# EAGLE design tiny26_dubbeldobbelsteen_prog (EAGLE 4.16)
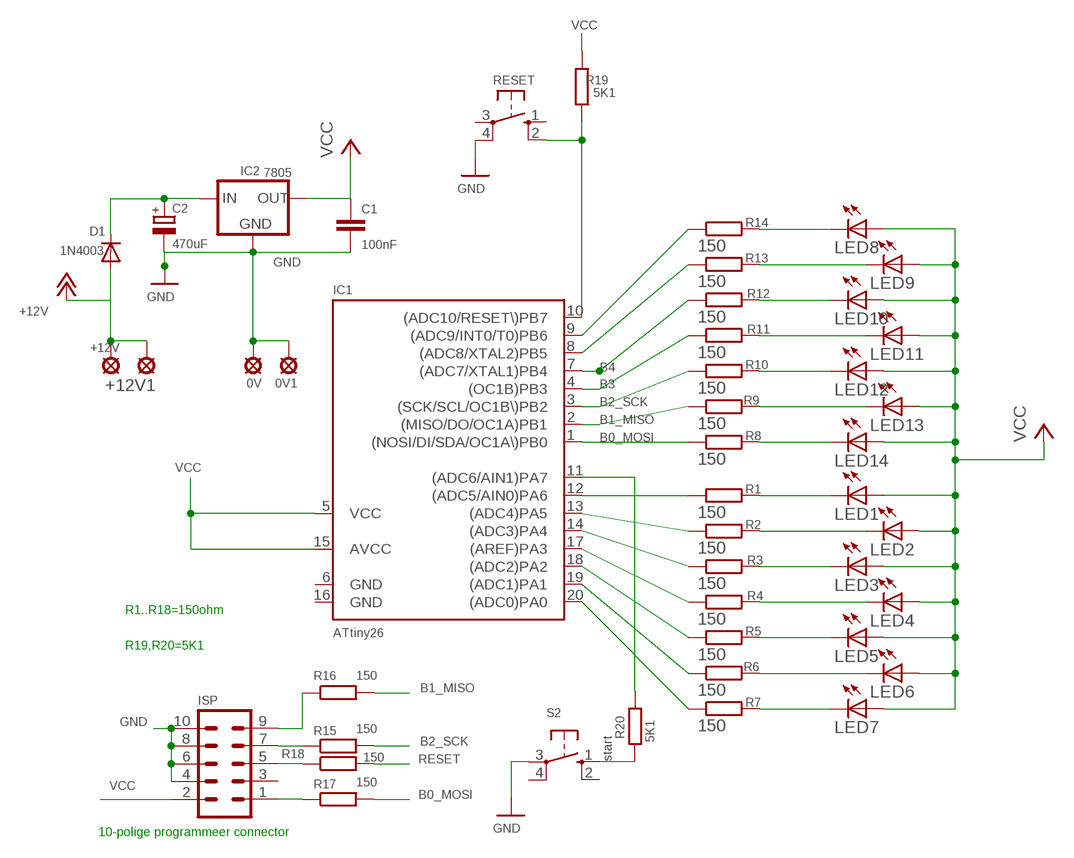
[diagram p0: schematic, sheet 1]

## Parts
0V  SE14  [SE14]
0V1  SE14  [SE14]
+12V  SE14  [SE14]
+12V1  SE14  [SE14]
C1  100nF  C-EU050-025X075  [C050-025X075]
C2  470uF  CPOL-EUE5-6  [E5-6]
D1  1N4003  DIODE-D-12.5  [D-12.5]
IC1  ATtiny26  TINY26LP  [DIL20]
IC2  7805  78XXS  [78XXS]
ISP  MA05-2  [MA05-2]
LED1  LED3MM  [LED3MM]
LED2  LED3MM  [LED3MM]
LED3  LED3MM  [LED3MM]
LED4  LED3MM  [LED3MM]
LED5  LED3MM  [LED3MM]
LED6  LED3MM  [LED3MM]
LED7  LED3MM  [LED3MM]
LED8  LED3MM  [LED3MM]
LED9  LED3MM  [LED3MM]
LED10  LED3MM  [LED3MM]
LED11  LED3MM  [LED3MM]
LED12  LED3MM  [LED3MM]
LED13  LED3MM  [LED3MM]
LED14  LED3MM  [LED3MM]
R1  150  R-EU_0207/10  [0207/10]
R2  150  R-EU_0207/10  [0207/10]
R3  150  R-EU_0207/10  [0207/10]
R4  150  R-EU_0207/10  [0207/10]
R5  150  R-EU_0207/10  [0207/10]
R6  150  R-EU_0207/10  [0207/10]
R7  150  R-EU_0207/10  [0207/10]
R8  150  R-EU_0207/10  [0207/10]
R9  150  R-EU_0207/10  [0207/10]
R10  150  R-EU_0207/10  [0207/10]
R11  150  R-EU_0207/10  [0207/10]
R12  150  R-EU_0207/10  [0207/10]
R13  150  R-EU_0207/10  [0207/10]
R14  150  R-EU_0207/10  [0207/10]
R15  150  R-EU_0207/10  [0207/10]
R16  150  R-EU_0207/10  [0207/10]
R17  150  R-EU_0207/10  [0207/10]
R18  150  R-EU_0207/10  [0207/10]
R19  5K1  R-EU_0207/10  [0207/10]
R20  5K1  R-EU_0207/10  [0207/10]
RESET  10-XX  [B3F-10XX]
S2  start  10-XX  [B3F-10XX]

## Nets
+12V: +12V1.MP +12V.MP D1.A
B0_MOSI: IC1.1((NOSI/DI/SDA/OC1A\)PB0) R8.1 R17.2
B1_MISO: IC1.2((MISO/DO/OC1A)PB1) R9.1 R16.2
B2_SCK: IC1.3((SCK/SCL/OC1B\)PB2) R10.1 R15.2
B3: IC1.4((OC1B)PB3) R11.1
B4: IC1.7((ADC7/XTAL1)PB4) R12.1
GND: 0V1.MP 0V.MP C1.2 C2.- IC2.GND ISP.4 ISP.6 ISP.8 ISP.10 RESET.4(P1) S2.3(P)
N$1: ISP.1 R17.1
N$3: R20.1 S2.1(S)
N$4: ISP.5 R18.1
N$5: LED7.K(C) R7.2
N$6: LED6.K(C) R6.2
N$7: LED5.K(C) R5.2
N$8: LED4.K(C) R4.2
N$9: LED3.K(C) R3.2
N$10: C2.+ D1.C IC2.IN
N$11: LED2.K(C) R2.2
N$12: LED1.K(C) R1.2
N$13: ISP.7 R15.1
N$14: IC1.20((ADC0)PA0) R7.1
N$15: IC1.19((ADC1)PA1) R6.1
N$16: ISP.9 R16.1
N$17: IC1.18((ADC2)PA2) R5.1
N$18: IC1.17((AREF)PA3) R4.1
N$19: IC1.14((ADC3)PA4) R3.1
N$20: IC1.13((ADC4)PA5) R2.1
N$21: IC1.12((ADC5/AIN0)PA6) R1.1
N$23: LED14.K(C) R8.2
N$24: LED13.K(C) R9.2
N$25: LED12.K(C) R10.2
N$26: LED11.K(C) R11.2
N$27: LED10.K(C) R12.2
N$28: LED9.K(C) R13.2
N$29: LED8.K(C) R14.2
N$30: IC1.8((ADC8/XTAL2)PB5) R13.1
N$31: IC1.9((ADC9/INT0/T0)PB6) R14.1
N$62: IC1.11((ADC6/AIN1)PA7) R20.2
RESET: IC1.10((ADC10/RESET\)PB7) R18.2 R19.1 RESET.2(S1)
VCC: C1.1 IC1.5(VCC) IC1.15(AVCC) IC2.OUT ISP.2 LED1.A LED2.A LED3.A LED4.A LED5.A LED6.A LED7.A LED8.A LED9.A LED10.A LED11.A LED12.A LED13.A LED14.A R19.2
Unconnected: ISP.3 RESET.1(S) RESET.3(P) S2.2(S1) S2.4(P1)

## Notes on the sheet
- R1..R18=150ohm
- R19,R20=5K1
- 10-polige programmeer connector

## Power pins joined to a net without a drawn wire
GND: IC1.6(GND) IC1.16(GND)

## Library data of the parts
0V 0V1 +12V +12V1 = solpad:SE14: SOLDER PAD
C1 = rcl:C-EU: CAPACITOR, European symbol
C2 = rcl:CPOL-EU: POLARIZED CAPACITOR, European symbol
D1 = diode:DIODE-: DIODE
IC1 = atmel:TINY26*: 8-bit AVR Microcontroller with 2K Bytes Flash
IC2 = v-reg:78XXS: VOLTAGE REGULATOR
ISP = con-lstb:MA05-2: PIN HEADER
LED1-LED14 = led:LED: LED
R1-R20 = rcl:R-EU_: RESISTOR, European symbol
RESET S2 = switch-omron:10-XX: OMRON SWITCH

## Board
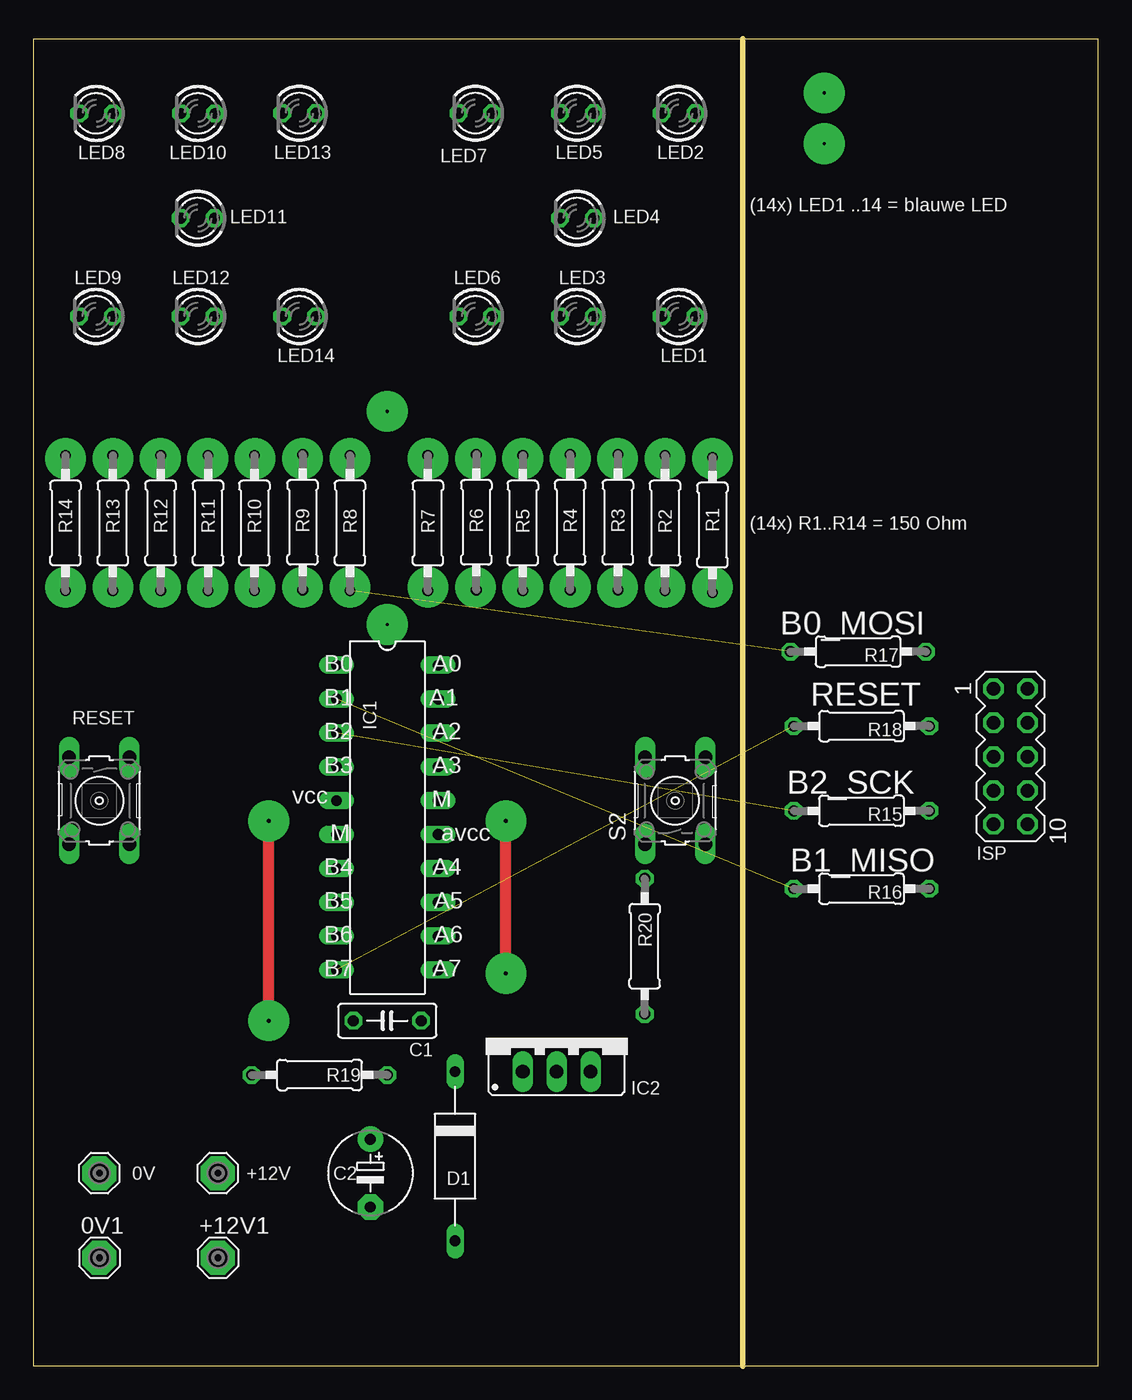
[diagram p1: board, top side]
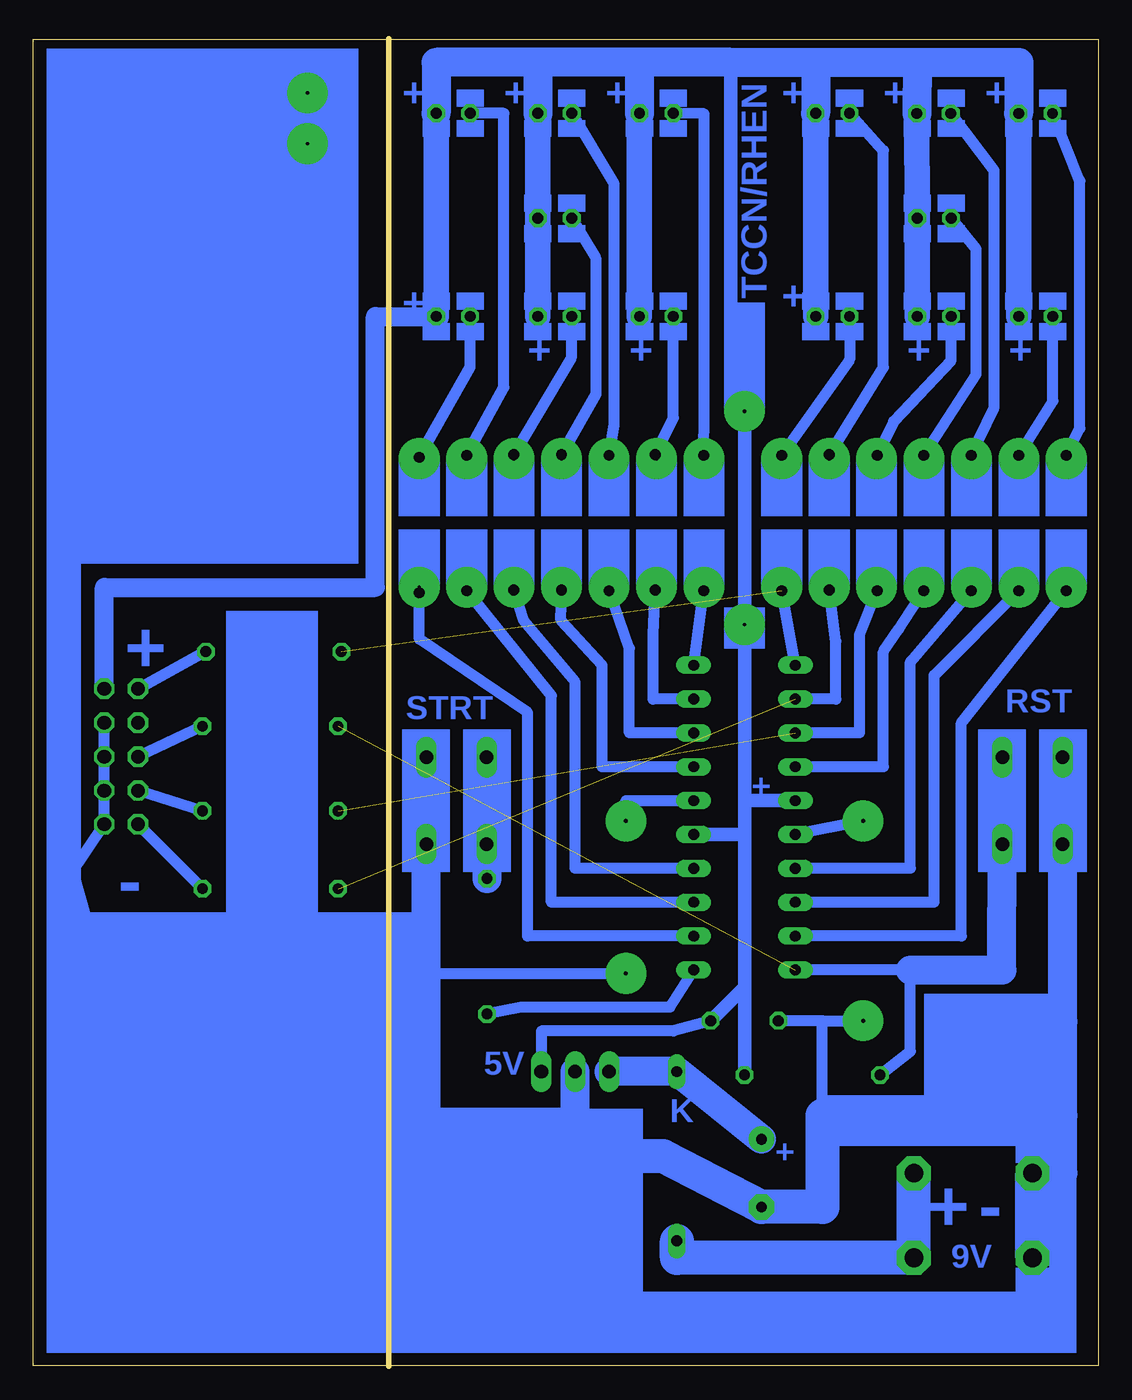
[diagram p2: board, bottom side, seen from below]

Size 79.86 x 99.57 mm. Coordinates in mm from the lower left corner, seen from the top.
Outline: 53.21,99.57 53.21,0
Outline: 0,0.04 79.86,0.04 79.86,99.53 0,99.53 0,0.04
Copper layers (1*16): Top 0.035mm / dielectric 1.5mm / Bottom 0.035mm
Design rules "default": minimum track width 24mil, minimum drill 24mil, track to track 15mil, track to pad 15mil, pad to pad 15mil, via to via 15mil, smd to smd 8mil, copper to edge 15mil, drill to drill 8mil, minimum pad ring 10mil, minimum via ring 8mil, stop-mask expansion 4mil, vias tented up to drill 0mil, thermal gap 10mil

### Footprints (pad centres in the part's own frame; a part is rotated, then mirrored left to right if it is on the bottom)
SE14 = drill 1.397 pad 2.54 octagon: MP 0,0
C050-025X075 = drill 0.813 octagon: 1 -2.54,0; 2 2.54,0
E5-6 = drill 0.813 pad 1.905 round: + -2.54,0 | drill 0.813 pad 1.905 octagon: - 2.54,0
D-12.5 = drill 0.813 long: A 6.35,0; C -6.35,0
DIL20 = drill 0.813 long: 1 -11.43,-3.81; 2 -8.89,-3.81; 3 -6.35,-3.81; 4 -3.81,-3.81; 5 -1.27,-3.81; 6 1.27,-3.81; 7 3.81,-3.81; 8 6.35,-3.81; 9 8.89,-3.81; 10 11.43,-3.81; 11 11.43,3.81; 12 8.89,3.81; 13 6.35,3.81; 14 3.81,3.81; 15 1.27,3.81; 16 -1.27,3.81; 17 -3.81,3.81; 18 -6.35,3.81; 19 -8.89,3.81; 20 -11.43,3.81
78XXS = drill 1.016 long: GND 0,-2.54; IN -2.54,-2.54; OUT 2.54,-2.54
MA05-2 = drill 1.016 octagon: 1 -5.08,-1.27; 2 -5.08,1.27; 3 -2.54,-1.27; 4 -2.54,1.27; 5 0,-1.27; 6 0,1.27; 7 2.54,-1.27; 8 2.54,1.27; 9 5.08,-1.27; 10 5.08,1.27
LED3MM = drill 0.813 octagon: A -1.27,0; K 1.27,0
0207/10 = drill 0.813 octagon: 1 -5.08,0; 2 5.08,0
B3F-10XX = drill 1.016 long: 1 -3.251,2.261; 2 3.251,2.261; 3 -3.251,-2.261; 4 3.251,-2.261

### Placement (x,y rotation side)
0V  4.95,14.48 180 top
0V1  4.95,8.13 0 top
+12V  13.84,14.48 180 top
+12V1  13.84,8.13 0 top
C1  26.54,25.91 180 top
C2  25.27,14.48 270 top
D1  31.62,15.75 270 top
IC1  26.54,41.15 270 top
IC2  39.24,24.64 0 top
ISP  73.27,45.72 270 top
LED1  48.38,78.74 180 top
LED2  48.38,93.98 180 top
LED3  40.76,78.74 180 top
LED4  40.76,86.11 180 top
LED5  40.76,93.98 180 top
LED6  33.14,78.74 180 top
LED7  33.14,93.98 180 top
LED8  4.71,93.96 180 top
LED9  4.69,78.74 180 top
LED10  12.35,93.96 180 top
LED11  12.31,86.11 180 top
LED12  12.31,78.74 180 top
LED13  19.93,93.98 180 top
LED14  19.93,78.74 180 top
R1  50.92,63.09 90 top
R2  47.37,63.25 90 top
R3  43.84,63.3 90 top
R4  40.25,63.3 90 top
R5  36.7,63.25 90 top
R6  33.22,63.3 90 top
R7  29.59,63.25 90 top
R8  23.74,63.25 90 top
R9  20.19,63.3 90 top
R10  16.58,63.25 90 top
R11  13.1,63.25 90 top
R12  9.55,63.25 90 top
R13  5.96,63.25 90 top
R14  2.41,63.25 90 top
R15  62.1,41.66 180 top
R16  62.1,35.81 180 top
R17  61.84,53.59 180 top
R18  62.1,48.01 180 top
R19  21.46,21.84 0 top
R20  45.84,31.5 270 top
RESET  4.95,42.42 270 top
S2  48.13,42.42 90 top

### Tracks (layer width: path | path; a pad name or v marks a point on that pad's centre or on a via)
+12V
  Bottom 2.54: +12V.MP +12V1.MP 31.62,8.13 D1.A
B0_MOSI  (1 unrouted)
  Bottom 0.813: IC1.1 R8.1
B1_MISO  (1 unrouted)
  Bottom 0.813: IC1.2 19.68,50.04 19.68,54.36 R9.1
B2_SCK  (1 unrouted)
  Bottom 0.813: IC1.3 17.9,47.5 17.9,54.86 R10.1
B3
  Bottom 0.813: IC1.4 16.12,44.96 16.12,53.59 14.96,55.3 R11.1
B4
  Bottom 0.813: IC1.7 14.09,37.34 14.09,52.83 R12.1
GND  (via drill 0.3 pad 3.05)
  Top 0.813: v35.43,29.46 v35.43,40.89 | v17.65,25.91 v17.65,40.89
  Bottom 0.406: 2.66,18.8 20.7,18.8
  Bottom 0.813: v35.43,40.89 35.43,42.42 IC1.16 | v17.65,40.89 IC1.6 | 50.41,29.46 v35.43,29.46 | 20.7,25.91 v17.65,25.91 | 20.7,18.8 20.7,25.91 | 20.7,25.91 C1.2 | 35.43,15.75 35.43,18.29 39.24,18.29 | ISP.4 ISP.6 ISP.8 ISP.10 77.08,36.83
  Bottom 1.422: 77.08,36.83 75.31,30.48 50.67,30.48 50.41,30.48
  Bottom 2.184: S2.3 50.41,30.48 50.41,29.46 50.41,18.29 39.24,18.29 IC2.GND | RESET.4 2.66,25.83 2.66,18.8 2.66,14.48 0V.MP
  Bottom 2.54: 35.43,15.75 32.63,15.75 C2.- 20.7,11.94 20.7,18.8 | 0V1.MP 0V.MP
N$1
  Bottom 0.813: R17.1 ISP.1
N$2  (via drill 0.25 pad 3.05)
  other vias: 2.41,68.07
N$3
  Bottom 0.813: 45.84,39.12 S2.1
  Bottom 2.184: R20.1 45.84,39.12
N$4
  Bottom 0.813: R18.1 ISP.5
N$5
  Bottom 0.813: LED7.K 29.56,93.93 29.56,71.58 R7.2
N$6
  Bottom 0.813: R6.2 31.87,71.12 LED6.K
N$7
  Bottom 0.813: LED5.K 36.32,88.67 36.32,70.61 R5.2
N$8
  Bottom 0.813: LED4.K 37.66,83.06 37.66,72.9 R4.2
N$9
  Bottom 0.813: LED3.K 39.49,75.69 R3.2
N$10
  Bottom 2.184: C2.+ D1.C IC2.IN
N$11
  Bottom 0.813: LED2.K 44.57,93.98 44.57,73.41 R2.2
N$12
  Bottom 0.813: R1.2 47.11,74.93 LED1.K
N$13
  Bottom 0.813: R15.1 ISP.7
N$14
  Bottom 0.813: IC1.20 R7.1
N$15
  Bottom 0.813: IC1.19 33.4,50.04 33.4,54.86 R6.1
N$16
  Bottom 0.813: R16.1 ISP.9
N$17
  Bottom 0.813: IC1.18 35.17,47.5 35.17,53.85 R5.1
N$18
  Bottom 0.813: IC1.17 37.21,44.96 37.21,52.58 40.3,55.96 R4.1
N$19
  Bottom 0.813: IC1.14 39.24,37.34 39.24,51.31 43.07,55.91 R3.1
N$20
  Bottom 0.813: IC1.13 41.02,34.8 41.02,50.29 R2.1
N$21
  Bottom 0.813: IC1.12 42.79,32.26 42.79,49.02 50.92,54.53 R1.1
N$22  (via drill 0.25 pad 3.05)
  other vias: 5.96,68.07
N$23
  Bottom 0.813: LED14.K 18.66,75.51 R8.2
N$24
  Bottom 0.813: LED13.K 16.12,91.19 16.12,74.93 R9.2
N$25
  Bottom 0.813: R10.2 15.36,70.87 11.04,75.44 LED12.K
N$26
  Bottom 0.813: R11.2 9.16,74.4 9.16,83.8 LED11.K
N$27
  Bottom 0.813: LED10.K 7.82,89.69 7.82,71.91 R12.2
N$28
  Bottom 0.813: LED9.K 3.42,72.39 R13.2
N$29
  Bottom 0.813: LED8.K 1.39,88.9 1.39,70.36 R14.2
N$30
  Bottom 0.813: IC1.8 12.31,34.8 12.31,51.82 R13.1
N$31
  Bottom 0.813: IC1.9 10.28,32.26 10.28,48.26 R14.1
N$32  (via drill 0.25 pad 3.05)
  other vias: 9.52,68.07
N$33  (via drill 0.25 pad 3.05)
  other vias: 13.08,68.07
N$34  (via drill 0.25 pad 3.05)
  other vias: 2.41,58.42
N$35  (via drill 0.25 pad 3.05)
  other vias: 5.96,58.42
N$36  (via drill 0.25 pad 3.05)
  other vias: 9.52,58.42
N$37  (via drill 0.25 pad 3.05)
  other vias: 13.08,58.42
N$38  (via drill 0.25 pad 3.05)
  other vias: 16.63,68.07
N$39  (via drill 0.25 pad 3.05)
  other vias: 20.19,68.07
N$40  (via drill 0.25 pad 3.05)
  other vias: 23.74,68.07
N$41  (via drill 0.25 pad 3.05)
  other vias: 29.59,68.07
N$42  (via drill 0.25 pad 3.05)
  other vias: 33.14,68.07
N$43  (via drill 0.25 pad 3.05)
  other vias: 29.59,58.42
N$44  (via drill 0.25 pad 3.05)
  other vias: 23.74,58.42
N$45  (via drill 0.25 pad 3.05)
  other vias: 20.19,58.42
N$46  (via drill 0.25 pad 3.05)
  other vias: 16.63,58.42
N$47  (via drill 0.25 pad 3.05)
  other vias: 33.14,58.42
N$48  (via drill 0.25 pad 3.05)
  other vias: 36.7,68.07
N$49  (via drill 0.25 pad 3.05)
  other vias: 36.7,58.42
N$50  (via drill 0.25 pad 3.05)
  other vias: 40.25,68.07
N$51  (via drill 0.25 pad 3.05)
  other vias: 40.25,58.42
N$52  (via drill 0.25 pad 3.05)
  other vias: 43.81,68.07
N$53  (via drill 0.25 pad 3.05)
  other vias: 43.81,58.42
N$54  (via drill 0.25 pad 3.05)
  other vias: 47.37,68.07
N$55  (via drill 0.25 pad 3.05)
  other vias: 47.37,58.42
N$56  (via drill 0.25 pad 3.05)
  other vias: 50.92,68.07
N$57  (via drill 0.25 pad 3.05)
  other vias: 50.92,58.42
N$58  (via drill 0.25 pad 3.05)
  other vias: 26.54,71.63
N$59  (via drill 0.25 pad 3.05)
  other vias: 26.54,55.63
N$60  (via drill 0.25 pad 3.05)
  other vias: 59.3,95.5
N$61  (via drill 0.25 pad 3.05)
  other vias: 59.3,91.69
N$62
  Bottom 0.813: IC1.11 32.13,26.92 43.3,26.92 R20.2
RESET  (1 unrouted)
  Bottom 0.813: IC1.10 14.09,29.72 14.09,23.62 R19.1
  Bottom 2.184: RESET.2 7.23,29.72 14.09,29.72
VCC
  Bottom 0.813: IC2.OUT 41.78,25.15 31.87,25.15 C1.1
  Bottom 1.016: 26.54,42.42 IC1.5 | 26.54,42.42 26.54,75.69 27.55,75.69 27.55,97.79 | 26.54,28.45 26.54,39.88 | 26.54,39.88 26.54,42.42 | 26.54,28.45 C1.1 | 26.54,39.88 IC1.15 | R19.2 26.54,28.45 | LED8.A 5.96,93.98
  Bottom 1.422: ISP.2 74.54,58.42 54.22,58.42 54.22,78.74 LED1.A
  Bottom 1.93: LED2.A LED1.A | LED13.A LED14.A | LED7.A LED6.A | LED3.A LED4.A LED5.A | LED12.A LED11.A LED10.A | 5.96,93.98 LED9.A
  Bottom 2.184: 13.58,97.79 5.96,97.79 LED8.A | 21.2,97.79 LED13.A | 21.2,97.79 13.58,97.79 | 21.2,97.79 27.55,97.79 34.41,97.79 | 34.41,97.79 42.03,97.79 | LED2.A 49.65,97.79 42.03,97.79 | 34.41,97.79 LED7.A | 42.03,97.79 LED5.A | 13.58,97.79 LED10.A
(copper drawn outside any net)
  shapes: Bottom area x109

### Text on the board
Bottom: TCCN/RHEN | + | + | + | + | + | + | + | + | + | + | + | + | + | RST | STRT | + | - | 5V | K | + | - | + | 9V
tNames: (14x) LED1 ..14 = blauwe LED | (14x) R1..R14 = 150 Ohm | B0_MOSI | B0 | A0 | B1 | A1 | RESET | B2 | A2 | B3 | A3 | vcc | M | B2_SCK | M | avcc | B4 | A4 | B1_MISO | B5 | A5 | B6 | A6 | B7 | A7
